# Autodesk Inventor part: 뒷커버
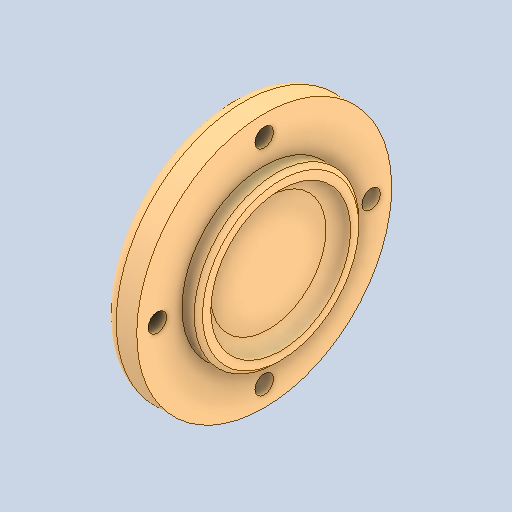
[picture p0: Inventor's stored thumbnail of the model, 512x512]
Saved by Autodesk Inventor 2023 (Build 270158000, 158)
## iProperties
Created: 2024-09
Part Number: 뒷커버
Material: 알루미늄 6061
Document SubType Name: Modeling
Designer: home
Density: 2.7 g/cm^3
Appearance: 기본값
Author: jhkim
Sending System: Autodesk Inventor 2025
Preprocessor: ST-DEVELOPER v20
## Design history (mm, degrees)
node "뒷커버1"
node "솔리드2"
node "솔리드1"
